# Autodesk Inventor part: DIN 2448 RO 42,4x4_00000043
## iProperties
Created: 2006-02
Part Number: DIN 2448 RO 42,4x4_00000043
Material: Default
Document SubType Name: Modeling
Designer: FranzK
Stock Number: DIN 2448 RO 42,4x4
Mass: 75.7986 g
Surface Area: 388.644 cm^2
Volume: 75.7986 cm^3
Density: 1 g/cm^3
G_L: 157.080 mm
G_W: 42.400 mm
G_H: 42.400 mm
AFG_Item: 42.4 x 4
CSToolsMass: 0.1
CSToolsVolume: 75799.0
CSToolsArea: 389.0
Author: FranzK
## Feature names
1. AFG_Detailed_DIN 2448 RO 42,4x4_00000043
2. AFG_Simplified_DIN 2448 RO 42,4x4_00000043
